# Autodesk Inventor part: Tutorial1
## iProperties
Shininess: 77.0
Length Units: 11269
Angle Units: 11279
Time Units: 11290
Mass Units: 11283
Length Display Precision: 3
Angle Display Precision: 2
Created: 2001-12
Part Number: Tutorial1
Document SubType Name: Modeling
Designer: Renu Muthoo
Density: 0.0
Volumn: 0.0
Area: 0.0
PropertySet Name: Model Information
Control State: 0
Master: False
Checked Out: False
Author: Renu Muthoo
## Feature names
1. Extrusion1
2. Extrusion2
3. Fillet1
